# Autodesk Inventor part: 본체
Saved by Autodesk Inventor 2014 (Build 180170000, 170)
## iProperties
Created: 2026-05
Part Number: 본체
Material: 일반
Document SubType Name: Modeling
Designer: dg
Density: 1 g/cm^3
Appearance: 기본값
Author: dg
Author: jhkim
Creation Date: 2026-04-23
Sending System: Autodesk Inventor 2027
Preprocessor: ST-DEVELOPER v20.1
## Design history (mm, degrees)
node "본체1"
node "솔리드1"
node "기준1"
